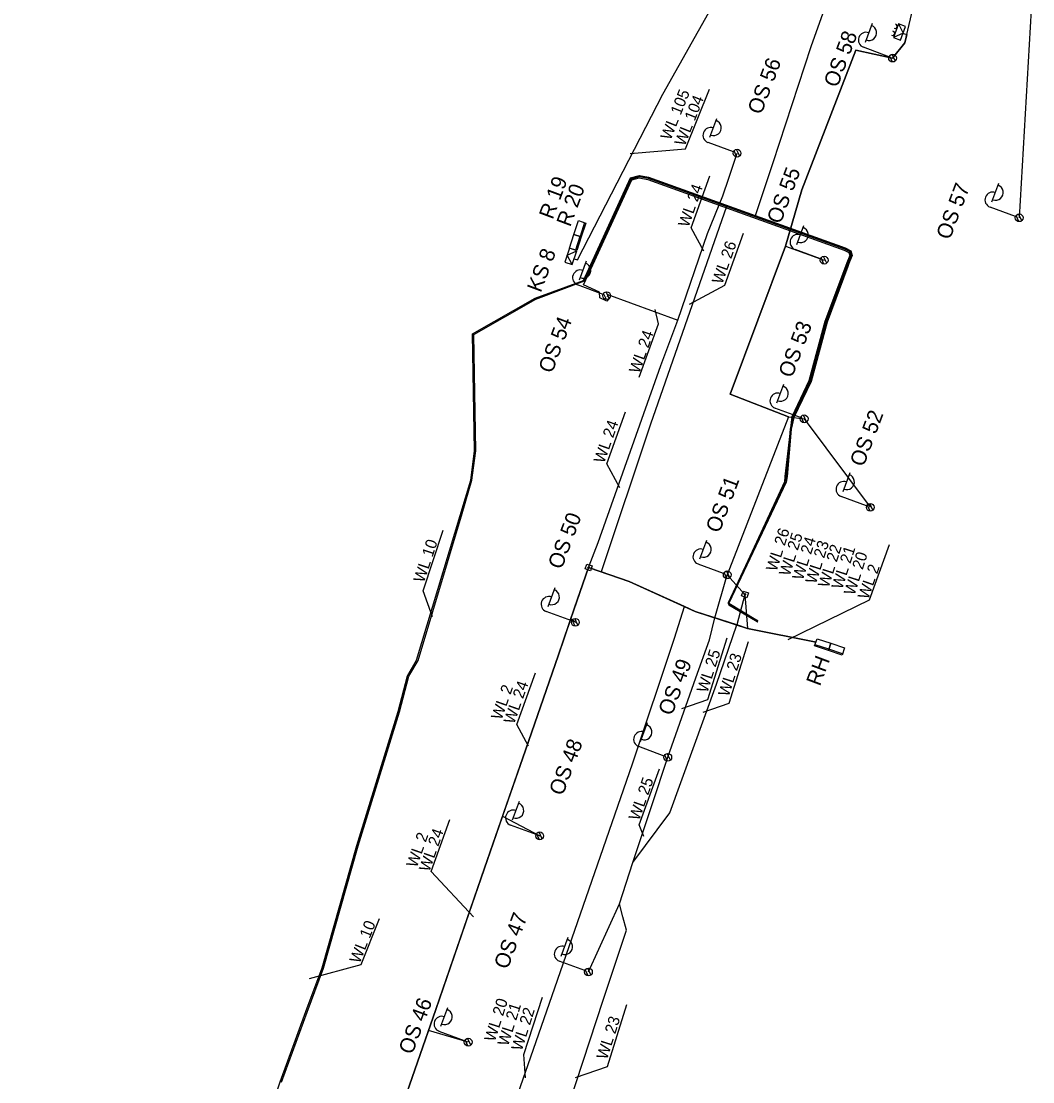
# Model space of a CAD drawing. Extents: x -695448 to -695200, y -1124997 to -1123857.
# Drawn here: x -695381.4 to -695248.1, y -1124245 to -1124105.2 of the extents above; entities that cross this region are included whole.
import ezdxf

# ---------------------------------------------------------------- set-up
doc = ezdxf.new("R2010")
doc.units = 0
doc.layers.add('Vrstva 26', color=7, linetype='Continuous')

msp = doc.modelspace()

# ---------------------------------------------------------------- linework, layer by layer
at = {"layer": 'Vrstva 26'}
for p, q in [((-695270.17, -1124108), (-695269.25, -1124105.5)), ((-695267.07, -1124109.91), (-695270.42, -1124108.67)), ((-695266.62, -1124110.6), (-695266.99, -1124109.78)), ((-695266.25, -1124110.47), (-695266.66, -1124109.58)), ((-695290.66, -1124120.53), (-695289.73, -1124118.04)), ((-695287.55, -1124122.45), (-695290.9, -1124121.21)), ((-695287.1, -1124123.13), (-695287.47, -1124122.32)), ((-695286.73, -1124123.01), (-695287.14, -1124122.12)), ((-695253.5, -1124129.04), (-695252.58, -1124126.55)), ((-695250.39, -1124130.96), (-695253.75, -1124129.72)), ((-695249.94, -1124131.64), (-695250.32, -1124130.83)), ((-695249.58, -1124131.52), (-695249.99, -1124130.63)), ((-695307.18, -1124131.76), (-695307.76, -1124133.58)), ((-695279.19, -1124134.63), (-695278.26, -1124132.14)), ((-695307.77, -1124133.58), (-695308.35, -1124135.4)), ((-695280.71, -1124134.89), (-695275.6, -1124136.72)), ((-695276.08, -1124136.54), (-695279.43, -1124135.3)), ((-695307.83, -1124139.31), (-695306.91, -1124136.81)), ((-695275.63, -1124137.23), (-695276, -1124136.42)), ((-695275.26, -1124137.11), (-695275.67, -1124136.22)), ((-695304.72, -1124141.22), (-695308.08, -1124139.98)), ((-695304.27, -1124141.91), (-695304.65, -1124141.09)), ((-695303.91, -1124141.78), (-695304.32, -1124140.89)), ((-695304.24, -1124141.19), (-695294.89, -1124144.62)), ((-695281.83, -1124155.53), (-695280.91, -1124153.04)), ((-695278.72, -1124157.45), (-695282.08, -1124156.21)), ((-695280.29, -1124157.37), (-695288.37, -1124178.17)), ((-695280.29, -1124157.37), (-695278.24, -1124157.62)), ((-695278.27, -1124158.13), (-695278.65, -1124157.32)), ((-695277.91, -1124158.01), (-695278.32, -1124157.12)), ((-695278.24, -1124157.62), (-695269.53, -1124169.28)), ((-695322.16, -1124165.7), (-695321.65, -1124161.83)), ((-695273.11, -1124167.19), (-695272.19, -1124164.69)), ((-695270.01, -1124169.1), (-695273.36, -1124167.86)), ((-695269.56, -1124169.79), (-695269.93, -1124168.97)), ((-695269.19, -1124169.66), (-695269.6, -1124168.77)), ((-695291.96, -1124176.08), (-695291.04, -1124173.59)), ((-695288.85, -1124178), (-695292.21, -1124176.75)), ((-695288.04, -1124178.56), (-695288.45, -1124177.67)), ((-695288.4, -1124178.68), (-695288.78, -1124177.87)), ((-695286.03, -1124180.77), (-695288.37, -1124178.17)), ((-695311.96, -1124182.34), (-695311.04, -1124179.85)), ((-695286.03, -1124180.77), (-695287.1, -1124184.77)), ((-695308.85, -1124184.26), (-695312.21, -1124183.01)), ((-695308.95, -1124183.92), (-695308.37, -1124184.43)), ((-695308.4, -1124184.94), (-695308.78, -1124184.13)), ((-695308.04, -1124184.82), (-695308.45, -1124183.93)), ((-695284.58, -1124184.07), (-695284.34, -1124184.21)), ((-695287.1, -1124184.77), (-695285.68, -1124185.23)), ((-695285.68, -1124185.23), (-695276.67, -1124187.03)), ((-695274.99, -1124187.98), (-695276.8, -1124187.38)), ((-695273.18, -1124188.57), (-695274.99, -1124187.98)), ((-695299.78, -1124200.13), (-695298.86, -1124197.64)), ((-695296.68, -1124202.05), (-695300.03, -1124200.81)), ((-695296.23, -1124202.73), (-695296.6, -1124201.92)), ((-695295.86, -1124202.61), (-695296.27, -1124201.72)), ((-695316.66, -1124210.48), (-695315.74, -1124207.99)), ((-695317.95, -1124209.97), (-695313.07, -1124212.57)), ((-695313.55, -1124212.39), (-695316.91, -1124211.15)), ((-695313.1, -1124213.08), (-695313.48, -1124212.26)), ((-695312.74, -1124212.95), (-695313.15, -1124212.07)), ((-695310.24, -1124228.42), (-695309.32, -1124225.93)), ((-695307.13, -1124230.33), (-695310.49, -1124229.09)), ((-695306.68, -1124231.02), (-695307.06, -1124230.2)), ((-695306.32, -1124230.9), (-695306.73, -1124230.01)), ((-695326.08, -1124237.66), (-695325.16, -1124235.17)), ((-695322.49, -1124239.75), (-695327.72, -1124238.21)), ((-695322.97, -1124239.57), (-695326.33, -1124238.33)), ((-695322.16, -1124240.14), (-695322.57, -1124239.25)), ((-695322.52, -1124240.26), (-695322.9, -1124239.44))]:
    msp.add_line(p, q, dxfattribs=at)
for points in [[(-695308.54, -1124136.53), (-695308.08, -1124136.67), (-695296.85, -1124114.85), (-695290.01, -1124102.66), (-695289.25, -1124100.57), (-695283.71, -1124085.37), (-695278.28, -1124071.41), (-695272.66, -1124055.34), (-695271.28, -1124050.37), (-695272.74, -1124049.86)], [(-695280.29, -1124157.37), (-695287.98, -1124154.37), (-695280.71, -1124134.89), (-695278.55, -1124127.46), (-695271.44, -1124109.04), (-695266.59, -1124110.09), (-695264.96, -1124108.09), (-695258.98, -1124082.56), (-695248.12, -1124095.56), (-695248.19, -1124101.4), (-695249.91, -1124131.13)], [(-695271.27, -1124091.42), (-695277.35, -1124108.62), (-695282.36, -1124123.87), (-695284.67, -1124130.89), (-695288.45, -1124129.65), (-695298.49, -1124158.33), (-695304.98, -1124177.78), (-695301.3, -1124179.05), (-695294, -1124182.36), (-695292.61, -1124182.99), (-695287.1, -1124184.77), (-695285.68, -1124185.23), (-695276.67, -1124187.03)], [(-695308.54, -1124136.53), (-695308.08, -1124136.67), (-695296.85, -1124114.85), (-695290.01, -1124102.66), (-695289.25, -1124100.57), (-695290.19, -1124100.22)], [(-695265.82, -1124105.57), (-695265.21, -1124106.81), (-695266.48, -1124107.38)], [(-695265.15, -1124106.84), (-695264.69, -1124106.96), (-695264.96, -1124108.09), (-695266.59, -1124110.09), (-695266.59, -1124110.09), (-695271.44, -1124109.04), (-695278.55, -1124127.46), (-695280.71, -1124134.89), (-695287.98, -1124154.37), (-695280.29, -1124157.37), (-695288.37, -1124178.17), (-695286.03, -1124180.77), (-695285.68, -1124185.23), (-695276.67, -1124187.03)], [(-695301.17, -1124122.67), (-695293.85, -1124122.03), (-695290.72, -1124114.18)], [(-695306.63, -1124177.21), (-695305.35, -1124173.92), (-695297.1, -1124150.61), (-695294.89, -1124144.62), (-695290.98, -1124133.22), (-695288.96, -1124128.26), (-695288.16, -1124125.93), (-695287.07, -1124122.62)], [(-695351.1, -1124256.32), (-695347.26, -1124244.97), (-695343.87, -1124235.73), (-695341.74, -1124229.94), (-695337.16, -1124213.82), (-695331.7, -1124196.19), (-695330.5, -1124191.5), (-695329.28, -1124189.42), (-695322.16, -1124165.7), (-695321.65, -1124161.83), (-695321.91, -1124146.42), (-695313.65, -1124141.73), (-695307.3, -1124139.38), (-695301.1, -1124125.87), (-695299.94, -1124125.55), (-695298.73, -1124125.78), (-695272.84, -1124135.11), (-695272.08, -1124135.5), (-695271.93, -1124136.09), (-695272.34, -1124137.16), (-695272.47, -1124137.54), (-695275.2, -1124144.88), (-695277.32, -1124152.69), (-695279.6, -1124157.46), (-695279.94, -1124158.99), (-695280.46, -1124165.24), (-695280.61, -1124165.97), (-695288.14, -1124181.92), (-695284.58, -1124184.07), (-695284.34, -1124184.21)], [(-695347.09, -1124245.03), (-695343.69, -1124235.79), (-695341.54, -1124230.01), (-695336.97, -1124213.87), (-695331.52, -1124196.23), (-695330.31, -1124191.55), (-695329.1, -1124189.47), (-695323.3, -1124170.1), (-695321.99, -1124165.72), (-695321.48, -1124161.85), (-695321.74, -1124146.52), (-695313.58, -1124141.86), (-695307.18, -1124139.44), (-695301.01, -1124125.99), (-695299.94, -1124125.69), (-695298.78, -1124125.92), (-695272.9, -1124135.23), (-695272.2, -1124135.59), (-695272.07, -1124136.07), (-695272.6, -1124137.49), (-695275.34, -1124144.83), (-695277.44, -1124152.65), (-695279.73, -1124157.41), (-695280.07, -1124158.97), (-695280.6, -1124165.22), (-695280.79, -1124165.93), (-695288.23, -1124181.88), (-695288.15, -1124182.1), (-695284.33, -1124184.38)], [(-695304.24, -1124141.4), (-695303.85, -1124141.64), (-695304.21, -1124142.13), (-695305.14, -1124141.66), (-695305.19, -1124140.95), (-695307.28, -1124139.98), (-695306.06, -1124137.34), (-695300.93, -1124126.12), (-695299.96, -1124125.85), (-695298.83, -1124126.08), (-695297.73, -1124126.5), (-695272.97, -1124135.38), (-695272.33, -1124135.69), (-695272.24, -1124136.08), (-695272.62, -1124137.08), (-695275.49, -1124144.81), (-695277.6, -1124152.61), (-695279.88, -1124157.38), (-695280.76, -1124165.22), (-695280.81, -1124165.94), (-695288.25, -1124181.89), (-695288.17, -1124182.11), (-695284.64, -1124184.21), (-695284.39, -1124184.36)], [(-695291.45, -1124135.51), (-695293.1, -1124132.46), (-695290.64, -1124125.61)], [(-695293.33, -1124142.51), (-695288.68, -1124140.01), (-695286.22, -1124133.16)], [(-695308.8, -1124137.29), (-695309.44, -1124136.06), (-695308.19, -1124135.47)], [(-695299.96, -1124152.11), (-695297.41, -1124145.1), (-695297.85, -1124143.22)], [(-695302.51, -1124166.71), (-695304.21, -1124163.55), (-695301.75, -1124156.7)], [(-695327.18, -1124183.72), (-695328.44, -1124180.3), (-695325.77, -1124172.28)], [(-695280.32, -1124186.71), (-695269.62, -1124181.49), (-695267, -1124174.17)], [(-695381.37, -1124394.21), (-695374.55, -1124374.32), (-695367.53, -1124354.51), (-695365.14, -1124347.4), (-695358.86, -1124329.48), (-695355.89, -1124320.48), (-695351.92, -1124309.4), (-695346.98, -1124293.92), (-695337.57, -1124266.71), (-695331.57, -1124249.34), (-695326.77, -1124235.46), (-695320.32, -1124216.82), (-695315.29, -1124202.27), (-695310.65, -1124188.85), (-695308.47, -1124182.54), (-695306.63, -1124177.21), (-695301.3, -1124179.05), (-695292.61, -1124182.99), (-695285.68, -1124185.23), (-695276.67, -1124187.03)], [(-695276.67, -1124187.03), (-695285.68, -1124185.23), (-695287.1, -1124184.77), (-695292.61, -1124182.99), (-695294, -1124182.36), (-695301.3, -1124179.05), (-695304.98, -1124177.78), (-695306.63, -1124177.21), (-695308.95, -1124183.92), (-695310.65, -1124188.85), (-695315.29, -1124202.27), (-695316.26, -1124205.04), (-695317.95, -1124209.97), (-695322.39, -1124222.79), (-695326.77, -1124235.46), (-695331.57, -1124249.34)], [(-695306.65, -1124230.51), (-695302.57, -1124221.53), (-695300.82, -1124216.06), (-695298.3, -1124208.59), (-695296.2, -1124202.22), (-695292.49, -1124191.76), (-695290.71, -1124186.76), (-695290.01, -1124183.83), (-695288.37, -1124178.17)], [(-695363.09, -1124389.47), (-695356.09, -1124369.39), (-695352.55, -1124358.94), (-695351.13, -1124358.25), (-695350.83, -1124357.36), (-695351.05, -1124356.58), (-695353.51, -1124355.7), (-695349.28, -1124343.38), (-695339.87, -1124316.03), (-695327.36, -1124279.65), (-695321.42, -1124262.37), (-695318.76, -1124254.71), (-695311.07, -1124232.58), (-695305.06, -1124215.26), (-695300.83, -1124203.07), (-695295.33, -1124186.53), (-695294, -1124182.36), (-695292.61, -1124182.99), (-695290.01, -1124183.83), (-695287.1, -1124184.77), (-695285.68, -1124185.23), (-695276.67, -1124187.03)], [(-695363.09, -1124389.47), (-695356.09, -1124369.39), (-695352.55, -1124358.94), (-695351.13, -1124358.25), (-695350.83, -1124357.36), (-695351.05, -1124356.58), (-695353.51, -1124355.7), (-695349.28, -1124343.38), (-695339.87, -1124316.03), (-695327.36, -1124279.65), (-695321.42, -1124262.37), (-695318.76, -1124254.71), (-695311.07, -1124232.58), (-695305.06, -1124215.26), (-695300.83, -1124203.07), (-695295.33, -1124186.53), (-695294, -1124182.36), (-695292.61, -1124182.99), (-695290.01, -1124183.83), (-695287.1, -1124184.77), (-695285.68, -1124185.23), (-695276.67, -1124187.03)], [(-695351.05, -1124356.58), (-695353.51, -1124355.7), (-695349.28, -1124343.38), (-695339.87, -1124316.03), (-695327.36, -1124279.65), (-695321.42, -1124262.37), (-695318.76, -1124254.71), (-695311.07, -1124232.58), (-695305.06, -1124215.26), (-695300.83, -1124203.07), (-695295.33, -1124186.53), (-695294, -1124182.36), (-695292.61, -1124182.99), (-695285.68, -1124185.23), (-695276.67, -1124187.03)], [(-695295.16, -1124294), (-695287.62, -1124268.59), (-695300.31, -1124263.86), (-695308.19, -1124258.46), (-695310.04, -1124250.44), (-695304.69, -1124234.24), (-695301.63, -1124225), (-695302.1, -1124223.26), (-695302.57, -1124221.53), (-695300.82, -1124216.06), (-695295.91, -1124209.52), (-695289.78, -1124192.6), (-695287.1, -1124184.77), (-695285.68, -1124185.23), (-695276.67, -1124187.03)], [(-695294.35, -1124195.78), (-695290.93, -1124194.6), (-695288.39, -1124186.47)], [(-695291.53, -1124196.28), (-695288.11, -1124195.1), (-695285.57, -1124186.97)], [(-695314.55, -1124200.76), (-695316.07, -1124197.92), (-695313.61, -1124191.07)], [(-695299.36, -1124212.65), (-695299.96, -1124211.12), (-695297.3, -1124203.73)], [(-695321.79, -1124223.26), (-695327.35, -1124217.27), (-695324.89, -1124210.42)], [(-695343.39, -1124231.38), (-695336.59, -1124229.54), (-695334.16, -1124223.45)], [(-695314.92, -1124244.45), (-695315.18, -1124241.37), (-695312.7, -1124233.81)], [(-695308.37, -1124244.4), (-695304.14, -1124242.94), (-695301.6, -1124234.8)]]:
    msp.add_lwpolyline(points, dxfattribs=at)
for points in [[(-695265.83, -1124105.57), (-695266.48, -1124107.38), (-695265.53, -1124107.72), (-695264.88, -1124105.91)], [(-695307.98, -1124131.51), (-695307.01, -1124131.82), (-695307.59, -1124133.64), (-695308.56, -1124133.33)], [(-695308.57, -1124133.33), (-695307.6, -1124133.64), (-695308.18, -1124135.46), (-695309.15, -1124135.15)], [(-695308.8, -1124137.29), (-695308.19, -1124135.47), (-695309.14, -1124135.15), (-695309.75, -1124136.97)], [(-695306.84, -1124176.76), (-695306.15, -1124177), (-695306.37, -1124177.64), (-695307.06, -1124177.4)], [(-695286.25, -1124180.31), (-695285.56, -1124180.55), (-695285.78, -1124181.19), (-695286.47, -1124180.95)], [(-695274.73, -1124187.18), (-695275.04, -1124188.15), (-695276.86, -1124187.55), (-695276.54, -1124186.59)], [(-695272.91, -1124187.78), (-695273.23, -1124188.75), (-695275.04, -1124188.15), (-695274.73, -1124187.18)]]:
    msp.add_lwpolyline(points, close=True, dxfattribs=at)
for centre, radius in [((-695266.59, -1124110.09), 0.511), ((-695266.59, -1124110.09), 0.511), ((-695287.07, -1124122.62), 0.511), ((-695287.07, -1124122.62), 0.511), ((-695249.91, -1124131.13), 0.511), ((-695249.91, -1124131.13), 0.511), ((-695275.6, -1124136.72), 0.511), ((-695275.6, -1124136.72), 0.511), ((-695304.24, -1124141.4), 0.511), ((-695304.24, -1124141.4), 0.511), ((-695278.24, -1124157.62), 0.511), ((-695278.24, -1124157.62), 0.511), ((-695269.53, -1124169.28), 0.511), ((-695269.53, -1124169.28), 0.511), ((-695306.63, -1124177.21), 0.0949), ((-695288.37, -1124178.17), 0.511), ((-695288.37, -1124178.17), 0.511), ((-695286.04, -1124180.75), 0.0949), ((-695308.37, -1124184.43), 0.511), ((-695308.37, -1124184.43), 0.511), ((-695296.2, -1124202.22), 0.511), ((-695296.2, -1124202.22), 0.511), ((-695313.07, -1124212.57), 0.511), ((-695313.07, -1124212.57), 0.511), ((-695306.65, -1124230.51), 0.511), ((-695306.65, -1124230.51), 0.511), ((-695322.49, -1124239.75), 0.511), ((-695322.49, -1124239.75), 0.511)]:
    msp.add_circle(centre, radius, dxfattribs=at)
for centre, radius, start, end in [((-695269.7, -1124106.75), 1.02, 249.0025, 70.4077), ((-695266.25, -1124105.9), 0.285, 238.078, 81.3114), ((-695270.07, -1124107.71), 1.02, 69.7051, 249.7051), ((-695266.59, -1124106.82), 0.285, 238.078, 81.3114), ((-695290.18, -1124119.29), 1.02, 249.0025, 70.4077), ((-695290.55, -1124120.25), 1.02, 69.7051, 249.7051), ((-695253.03, -1124127.8), 1.02, 249.0025, 70.4077), ((-695253.4, -1124128.76), 1.02, 69.7051, 249.7051), ((-695278.71, -1124133.39), 1.02, 249.0025, 70.4077), ((-695279.08, -1124134.34), 1.02, 69.7051, 249.7051), ((-695307.36, -1124138.06), 1.02, 249.0025, 70.4077), ((-695307.72, -1124139.02), 1.02, 69.7051, 249.7051), ((-695281.36, -1124154.29), 1.02, 249.0025, 70.4077), ((-695281.72, -1124155.25), 1.02, 69.7051, 249.7051), ((-695272.64, -1124165.94), 1.02, 249.0025, 70.4077), ((-695273.01, -1124166.9), 1.02, 69.7051, 249.7051), ((-695291.86, -1124175.79), 1.02, 69.7051, 249.7051), ((-695291.49, -1124174.84), 1.02, 249.0025, 70.4077), ((-695311.49, -1124181.1), 1.02, 249.0025, 70.4077), ((-695311.86, -1124182.06), 1.02, 69.7051, 249.7051), ((-695299.31, -1124198.89), 1.02, 249.0025, 70.4077), ((-695299.68, -1124199.85), 1.02, 69.7051, 249.7051), ((-695316.19, -1124209.24), 1.02, 249.0025, 70.4077), ((-695316.55, -1124210.19), 1.02, 69.7051, 249.7051), ((-695309.77, -1124227.18), 1.02, 249.0025, 70.4077), ((-695310.13, -1124228.13), 1.02, 69.7051, 249.7051), ((-695325.97, -1124237.37), 1.02, 69.7051, 249.7051), ((-695325.61, -1124236.42), 1.02, 249.0025, 70.4077)]:
    msp.add_arc(centre, radius, start, end, dxfattribs=at)

# ---------------------------------------------------------------- texts
for s, height, rotation, p in [('OS 58', 2, 69.4105, (-695273.86, -1124114.08)), ('OS 56', 2, 69.4105, (-695283.89, -1124117.64)), ('WL 105', 1.5, 68.1219, (-695295.84, -1124121.01)), ('WL 104', 1.5, 68.1219, (-695293.99, -1124121.79)), ('OS 55', 2, 69.4105, (-695281.35, -1124132.05)), ('R 19', 2, 69.4105, (-695311.36, -1124131.45)), ('R 20', 2, 69.4105, (-695309.06, -1124132.43)), ('WL 24', 1.5, 70.5598, (-695293.48, -1124132.49)), ('OS 57', 2, 69.4105, (-695259.05, -1124134.14)), ('WL 26', 1.5, 70.5598, (-695289.04, -1124139.98)), ('KS 8', 2, 69.4105, (-695312.93, -1124141.08)), ('OS 54', 2, 69.4105, (-695311.44, -1124151.73)), ('OS 53', 2, 69.4105, (-695279.83, -1124152.33)), ('WL 24', 1.5, 70.5598, (-695299.96, -1124151.75)), ('OS 52', 2, 69.4105, (-695270.42, -1124164.05)), ('WL 24', 1.5, 70.5598, (-695304.6, -1124163.59)), ('OS 51', 2, 69.4105, (-695289.4, -1124172.77)), ('OS 50', 2, 69.4105, (-695310.19, -1124177.56)), ('WL 26', 1.5, 72.2546, (-695281.89, -1124177.83)), ('WL 10', 1.5, 71.5223, (-695328.33, -1124179.31)), ('WL 25', 1.5, 72.2546, (-695280.17, -1124178.44)), ('WL 24', 1.5, 72.2546, (-695278.43, -1124178.98)), ('WL 23', 1.5, 72.2546, (-695276.7, -1124179.47)), ('WL 22', 1.5, 72.2546, (-695275.03, -1124179.98)), ('WL 21', 1.5, 72.2546, (-695273.24, -1124180.18)), ('WL 20', 1.5, 72.2546, (-695271.62, -1124180.97)), ('WL 2', 1.5, 70.5598, (-695269.81, -1124181.52)), ('WL 25', 1.5, 72.2546, (-695291, -1124193.82)), ('WL 23', 1.5, 72.2546, (-695288.18, -1124194.32)), ('RH', 2, 69.4105, (-695276.16, -1124192.94)), ('OS 49', 2, 69.4105, (-695295.66, -1124196.84)), ('WL 2', 1.5, 70.5598, (-695318.11, -1124197.4)), ('WL 24', 1.5, 70.5598, (-695316.46, -1124197.95)), ('OS 48', 2, 69.4105, (-695310.04, -1124207.38)), ('WL 25', 1.5, 70.5598, (-695299.98, -1124210.66)), ('WL 2', 1.5, 70.5598, (-695329.27, -1124216.86)), ('WL 24', 1.5, 70.5598, (-695327.62, -1124217.41)), ('WL 10', 1.5, 68.1219, (-695336.8, -1124229.49)), ('OS 47', 2, 69.4105, (-695317.3, -1124230.27)), ('OS 46', 2, 69.4105, (-695329.86, -1124241.49)), ('WL 20', 1.5, 72.4231, (-695318.99, -1124239.8)), ('WL 21', 1.5, 72.4231, (-695317.25, -1124240.38)), ('WL 22', 1.5, 72.4231, (-695315.44, -1124241)), ('WL 23', 1.5, 72.2546, (-695304.21, -1124242.15))]:
    msp.add_text(s, height=height, rotation=rotation, dxfattribs=at).set_placement(p)

doc.saveas('drawing.dxf')
